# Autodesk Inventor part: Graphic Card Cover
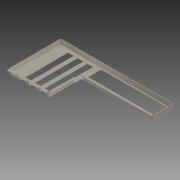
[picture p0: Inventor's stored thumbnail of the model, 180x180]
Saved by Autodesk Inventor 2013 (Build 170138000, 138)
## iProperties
Created: 2007-02
Part Number: Graphic Card Cover
Material: Allgemein
Document SubType Name: Sheet Metal
Designer: Autodesk, Inc.
Mass: 16.7691 g
Surface Area: 355.901 cm^2
Volume: 16.7691 cm^3
Density: 1 g/cm^3
Flat Pattern Width: 27.3453 cm
Flat Pattern Length: 14.293 cm
Flat Pattern Area: 390.846 cm^2
Sheet Metal Rule: 1 mm
Sheet Metal Width: 273.453 mm
Sheet Metal Length: 142.930 mm
Sheet Metal Area: 39084.554 mm^2
Author: Autodesk, Inc.
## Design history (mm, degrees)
node "Face1"
cut "Cut1" dims "d5" = 1 (= Thickness), "d6" = 0
node "Flange1"
node "Face2"
cut "Cut2" dims "d29" = 1 (= Thickness), "d30" = 0
pattern_linear "Rectangular Pattern1" dims "d33" = 21.5
node "Flange2"
node "Flange3"
feature "iFeature1:1" dims "d64" = 0.75, "d65" = 5, "d66" = 3.8, "d67" = 0.8, "d68" = 2.3, "d69" = 2.25, "d70" = 9, "d71" = 5, "d72" = 4.5 (= 0.5 x d70), "d73" = 1.68678, "d74" = 0.88678 (derived)
body "Solid1"
sketch "Sketch2"
  geometry: L1 (-37.75, 14.25)-(-37.75, -2.25); L2 (-37.75, -2.25)-(-36.75, -2.25); L3 (-37.75, 14.25)-(-31.75, 14.25); L4 (-31.75, 14.25)-(-31.75, 13.25); L5 (-36.75, 13.25)-(-36.75, -57.25) reference; L6 (125.75, 13.25)-(-36.75, 13.25) reference; L7 (-36.75, -2.25)-(-37.75, -2.25); L8 (-37.75, -2.25)-(-37.75, -2.24); L9 (-37.75, -2.24)-(-36.75, -2.24); L10 (-36.75, -2.24)-(-36.75, -2.25); L11 (-31.75, 13.25)-(-31.76, 13.25); L12 (-31.76, 13.25)-(-31.76, 14.25); L13 (-31.76, 14.25)-(-31.75, 14.25); L14 (-31.75, 14.25)-(-31.75, 13.25)
  constraints: 24 end point, 5 parallel, 4 perpendicular, 4 point on line, 2 horizontal, 1 vertical
  dimensions: "d16" = 5 distance between parallel lines of L4 L5; "d17" = 15.5 distance between parallel lines of L2 L6; "d18" = 1 distance of L3.end L4.end (= Thickness); "d19" = 1 distance of L1.end L2.end (= Thickness); "d78" = 0.01 distance of L9.end L2.end; "d79" = 0.01 distance of L4.end L11.end
sketch "Sketch1"
  geometry: L1 (-125.75, 57.25)-(125.75, 57.25); L2 (125.75, 57.25)-(125.75, 13.25); L3 (125.75, 13.25)-(-125.75, 13.25); L4 (-125.75, 13.25)-(-125.75, 57.25); L5 (125.75, 57.25)-(36.75, 57.25); L6 (36.75, 57.25)-(36.75, -57.25); L7 (36.75, -57.25)-(125.75, -57.25); L8 (125.75, -57.25)-(125.75, 57.25); L9 (125.75, -57.25)-(-125.75, 57.25); L10 (-115.25, 54.25)-(32.75, 54.25); L11 (32.75, 54.25)-(32.75, 17.25); L12 (32.75, 17.25)-(-115.25, 17.25); L13 (-115.25, 17.25)-(-115.25, 54.25); 2 further points
  constraints: 26 end point, 6 parallel, 3 horizontal, 3 perpendicular, 1 coincident, 1 midpoint
  dimensions: "d0" = 114.5 distance of L7.end L1.end; "d1" = 251.5 distance between parallel lines of L8 L4; "d2" = 162.5 distance between parallel lines of L6 L4; "d3" = 44 distance of L3.end L1.start; "d34" = 148 distance between parallel lines of L11 L13; "d35" = 37 distance of L12.end L10.start; "d36" = 10.5 distance between parallel lines of L4 L13; "d76" = 3 distance between parallel lines of L10 L1; "d77" = 4 distance between parallel lines of L3 L12 (derived)
face "Plate1" dims "Thickness" = 1
sketch "Sketch3"
  geometry: L1 through (78.75, 0) direction (-1, 6.86e-35); L2 through (0, -6.25) direction (0, -1); L3 (0, -12.5)-(157.5, -12.5); L4 (157.5, -12.5)-(157.5, 0)
  constraints: 6 end point, 1 horizontal, 1 perpendicular, 1 vertical
face "Plate2" dims "d7" = 1 (= BendReliefWidth), "d8" = 0.5 (= BendReliefDepth), "d9" = 2 (= MinimumRemnant), "d10" = 0.5 (= BendRadius), "d11" = 12.5, "d12" = 90 deg, "d13" = 0.5 (= BendRadius), "d14" = 4 (= CornerReliefSize), "d15" = 0.5, "d80" = 1 (= JacobiRadiusSize), "SeamGap" = 0.01, "Thickness" = 1
bend "Bend1" dims "d7" = 1 (= BendReliefWidth), "d8" = 0.5 (= BendReliefDepth), "d9" = 2 (= MinimumRemnant), "d10" = 0.5 (= BendRadius), "d11" = 12.5, "d12" = 90 deg, "d13" = 0.5 (= BendRadius), "SeamGap" = 0.01, "Thickness" = 1
feature "Corner1" dims "d11" = 12.5, "d12" = 90 deg, "d14" = 4 (= CornerReliefSize), "d15" = 0.5, "d80" = 1 (= JacobiRadiusSize)
face "Plate3" dims "d20" = 0.5 (= BendRadius), "d23" = 2 (= MinimumRemnant), "SeamGap" = 0.01, "Thickness" = 1
bend "Bend2" dims "d20" = 0.5 (= BendRadius), "d21" = 1 (= BendReliefWidth), "d22" = 0.5 (= BendReliefDepth), "d23" = 2 (= MinimumRemnant), "d24" = 0.5 (= BendRadius), "SeamGap" = 0.01, "Thickness" = 1
sketch "Sketch4"
  geometry: L1 (46.25, 49.75)-(59.25, 49.75); L2 (59.25, 49.75)-(59.25, -60.25); L3 (59.25, -60.25)-(46.25, -60.25); L4 (46.25, -60.25)-(46.25, 49.75); L5 (36.75, -2.24)-(36.75, 13.25) reference; L6 (-124.396, 57.25)-(124.396, 57.25) reference; 1 further point
  constraints: 8 end point, 2 parallel, 1 horizontal, 1 perpendicular
  dimensions: "d25" = 13 distance of L1.start L1.end; "d26" = 9.5 distance between parallel lines of L5 L4; "d27" = 110 distance of L1.end L2.end; "d28" = 7.5 distance between parallel lines of L6 L1
sketch "Sketch5"
  geometry: L1 through (43.146, 0) direction (-1, 4.12e-16); L2 through (0, -4) direction (-2.14e-31, -1); L3 (0, -8)-(86.293, -8); L4 (86.293, -8)-(86.293, 0)
  constraints: 6 end point, 1 horizontal, 1 perpendicular, 1 vertical
face "Plate4" dims "d37" = 1 (= BendReliefWidth), "d38" = 0.5 (= BendReliefDepth), "d39" = 2 (= MinimumRemnant), "d40" = 0.5 (= BendRadius), "d41" = 8, "d42" = 90 deg, "d43" = 0.5 (= BendRadius), "d44" = 4 (= CornerReliefSize), "d45" = 1 (= Thickness), "d81" = 1 (= JacobiRadiusSize), "SeamGap" = 0.01, "Thickness" = 1
bend "Bend3" dims "d37" = 1 (= BendReliefWidth), "d38" = 0.5 (= BendReliefDepth), "d39" = 2 (= MinimumRemnant), "d40" = 0.5 (= BendRadius), "d41" = 8, "d42" = 90 deg, "d43" = 0.5 (= BendRadius), "SeamGap" = 0.01, "Thickness" = 1
feature "Corner2" dims "d41" = 8, "d42" = 90 deg, "d44" = 4 (= CornerReliefSize), "d45" = 1 (= Thickness), "d81" = 1 (= JacobiRadiusSize)
sketch "Sketch6"
  geometry: L1 through (0, 26.823) direction (-1.66e-16, -1); L2 through (3, 0) direction (1, -6.57e-32); L3 (6, 0)-(6, 53.646); L4 (6, 53.646)-(0, 53.646)
  constraints: 6 end point, 1 horizontal, 1 perpendicular, 1 vertical
face "Plate5" dims "d46" = 1 (= BendReliefWidth), "d47" = 0.5 (= BendReliefDepth), "d48" = 2 (= MinimumRemnant), "d49" = 0.5 (= BendRadius), "d50" = 6, "d51" = 90 deg, "d52" = 0.5 (= BendRadius), "d53" = 4 (= CornerReliefSize), "d54" = 1 (= Thickness), "d82" = 1 (= JacobiRadiusSize), "SeamGap" = 0.01, "Thickness" = 1
bend "Bend4" dims "d46" = 1 (= BendReliefWidth), "d47" = 0.5 (= BendReliefDepth), "d48" = 2 (= MinimumRemnant), "d49" = 0.5 (= BendRadius), "d50" = 6, "d51" = 90 deg, "d52" = 0.5 (= BendRadius), "SeamGap" = 0.01, "Thickness" = 1
feature "Corner3" dims "d50" = 6, "d51" = 90 deg, "d53" = 4 (= CornerReliefSize), "d54" = 1 (= Thickness), "d82" = 1 (= JacobiRadiusSize)
sketch "Sketch7" dims "d62" = 10
  geometry: L1 (0, 0)-(86.293, 0) reference; L2 (86.293, 0)-(86.293, 6.5) reference; 3 further points
  constraints: 1 horizontal, 2 other
  dimensions: "d55" = 0.887 distance from line of L1 point (65.793, 0.887); "d56" = 20.5 distance from line of L2 point (65.793, 0.887); "d59" = 25 distance of point (65.793, 0.887) point (40.793, 0.887)
feature "Definition1" dims "d0" = 1 (derived)
other parameters: "BendRadius" = 0.5, "BendReliefWidth" = 1 (= Thickness), "BendReliefDepth" = 0.5 (= 0.5 x Thickness), "CornerReliefSize" = 4 (= 4 x Thickness), "MinimumRemnant" = 2 (= 2 x Thickness), "TransitionRadius" = 0.5 (= BendRadius), "JacobiRadiusSize" = 1 (= Thickness), "d4" = 0.5 (= BendRadius), "d75" = 0, "GapSize" = 1 (= Thickness), "BendRadius" = 0.5, "BendReliefDepth" = 0.5, "BendReliefWidth" = 1, "CornerReliefSize" = 4, "JacobiRadiusSize" = 1, "MinimumRemnant" = 2, "Thickness" = 1, "TransitionRadius" = 0.5, "GapSize" = 1
